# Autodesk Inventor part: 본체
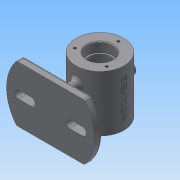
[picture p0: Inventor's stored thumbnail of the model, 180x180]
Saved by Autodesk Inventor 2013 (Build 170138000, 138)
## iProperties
Created: 2017-12
Part Number: 본체
Material: 일반
Document SubType Name: Modeling
Designer: Administrator
Density: 1 g/cm^3
Author: Administrator
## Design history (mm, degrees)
sketch "스케치1"
  geometry: L1 (0, 35)-(30, 35); L2 (30, 35)-(30, 0); L3 (0, 0)-(0, 35); L4 (0, 0)-(30, 0); 1 further point
  constraints: 8 end point, 2 horizontal, 1 coincident, 1 parallel, 1 perpendicular
  dimensions: "d4" = 30 distance of L1.start L1.end; "d6" = 35 distance of L1.end L2.end
revolve "회전1" sketch "스케치1" stored, may be unused: angle "d5" = 90 deg
sketch "스케치2"
  geometry: C1 r 30 at (0, 0) reference; 1 further point
  constraints: 1 vertical alignment
  dimensions: "d7" = 23 distance of C1.centre point (0, 23)
hole "구멍1" sketch "스케치2" at (0, 23) diameter "d8" = 3.242; stored, may be unused: countersink angle "d12" = 90 deg, drill point angle "d14" = 118 deg; dims "d9" = 8, "d10" = 4, "d11" = 2, "d13" = 10
hole "구멍2" diameter "d20" = 50; stored, may be unused: countersink angle "d24" = 90 deg, drill point angle "d26" = 0 deg; dims "d18" = 10, "d19" = 10, "d21" = 8, "d22" = 4, "d23" = 2, "d25" = 20
hole "구멍3" diameter "d29" = 28; stored, may be unused: countersink angle "d33" = 90 deg, drill point angle "d35" = 0 deg; dims "d30" = 8, "d31" = 32, "d32" = 12, "d34" = 15, "d36" = 10, "d37" = 10
fillet "모깎기1" dims "d38" = 0.3
chamfer "모따기1" distance "d39" = 1; stored, may be unused: second distance "d40" = 2, angle "d41" = 45 deg
fillet "모깎기2" dims "d42" = 3
node "작업 평면1"
sketch "스케치3"
  geometry: C1 r 8 at (0, 0); 1 further point
  constraints: 1 centre point, 1 coincident
  dimensions: "d44" = 16 diameter of C1
extrude "돌출1" join sketch "스케치3" stored distance "d46" = 10; taper "d47" = 0 deg
hole "구멍4" diameter "d50" = 8; stored, may be unused: countersink angle "d54" = 90 deg, drill point angle "d56" = 0 deg; dims "d51" = 8, "d52" = 32, "d53" = 12, "d55" = 20, "d57" = 10, "d58" = 10
chamfer "모따기2" distance "d59" = 1; stored, may be unused: second distance "d60" = 2, angle "d61" = 45 deg
node "작업 평면2"
sketch "스케치4"
  geometry: L1 (0, 35)-(42.426, 35); L2 (0, -35)-(42.426, -35); L3 (24, -5)-(40, -5); L4 (24, 5)-(40, 5); L5 (0, 35)-(0, -35); A1 r 55 centre (0, 0) between (42.426, -35) and (42.426, 35); A2 r 5 centre (24, 0) between (24, 5) and (24, -5); A3 r 5 centre (40, 0) between (40, -5) and (40, 5); 2 further points
  constraints: 10 end point, 6 point on circle, 4 tangent, 3 centre point, 2 coincident, 2 horizontal alignment, 1 equal radius, 1 horizontal, 1 midpoint, 1 parallel, 1 vertical
  dimensions: "d66" = 55 radius of A1; "d67" = 16 distance of A3.centre A2.centre; "d68" = 70 distance of L1.start L2.start; "d69" = 5 radius of A2; "d70" = 24 distance of point (0, 0) A2.centre
extrude "돌출2" join sketch "스케치4" distance "d71" = 10; taper "d72" = 0 deg
sketch "스케치5"
  geometry: L1 (5, 15)-(5, -15); L2 (-5, -15)-(-5, 15); A1 r 55 centre (0, 0) between (-42.426, 35) and (-42.426, -35) reference; A2 r 5 centre (0, 15) between (5, 15) and (-5, 15); A3 r 5 centre (0, -15) between (-5, -15) and (5, -15)
  constraints: 5 end point, 4 point on circle, 4 tangent, 2 centre point, 2 vertical alignment, 1 parallel
  dimensions: "d73" = 30 distance of A3.centre A2.centre; "d75" = 5 radius of A2; "d76" = 15 distance of A2.centre A1.centre (= 0.5 x d73)
extrude "돌출3" join sketch "스케치5" stored distance "d77" = 10; taper "d78" = 0 deg
node "작업 평면3"
sketch "스케치6"
  geometry: L1 (-30, 35)-(30, 35) reference; 2 further points
  constraints: 1 other
  dimensions: "d80" = 35 distance from line of L1 point (0, 0); "d81" = 30 horizontal distance of L1.end point (0, 0)
feature "엠보싱1" sketch "스케치6" dims "d82" = 0.5, "d83" = 0
fillet "모깎기3" dims "d84" = 3
fillet "모깎기4" dims "d85" = 3
fillet "모깎기5" dims "d86" = 5
node "솔리드1"
pattern_circular "원형 패턴1" dims angle "d16" = 360 deg
mirror "대칭1"
mirror "대칭2"
other parameters: "d43" = 37, "d62" = -62, "d79" = 31
